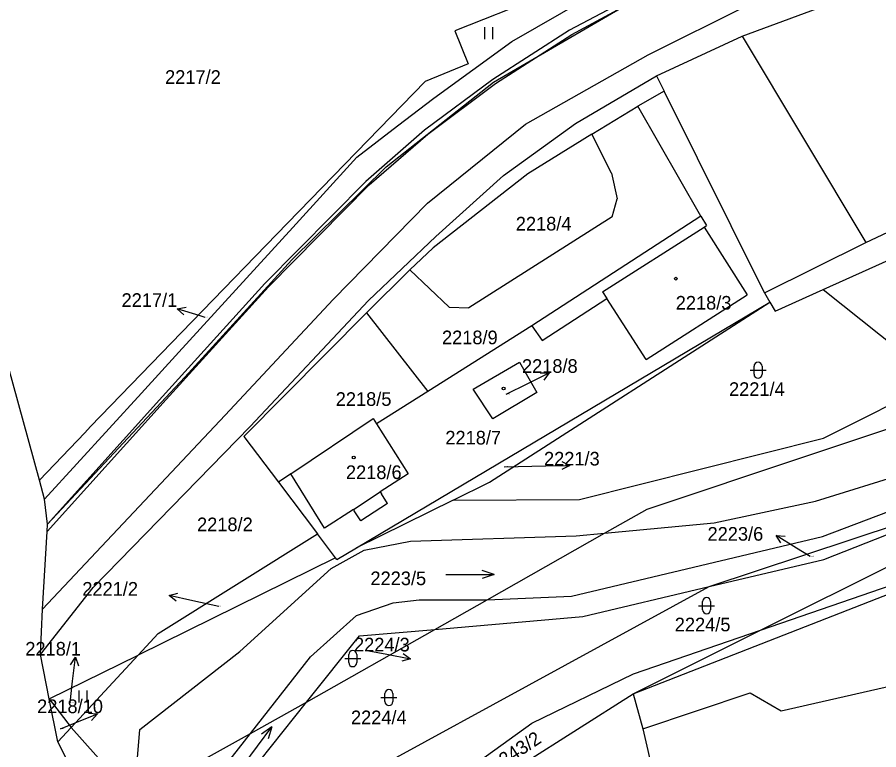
# Model space of a CAD drawing. Extents: x -785744 to -782822, y -1067550 to -1063910.
# Drawn here: x -785532.1 to -785424.6, y -1066082.7 to -1065991.3 of the extents above; entities that cross this region are included whole.
import ezdxf

# ---------------------------------------------------------------- set-up
doc = ezdxf.new("R2010")
doc.units = 0
for name, color, linetype in [('Hranice obce', 7, 'Continuous'), ('Hranice parcel', 7, 'Continuous'), ('Parcelní čísla', 7, 'Continuous'), ('Pop_ČP_popisy', 7, 'Continuous'), ('Vnitřní kresba', 7, 'Continuous'), ('Věcná břemena k části', 7, 'Continuous'), ('Značky budov', 7, 'Continuous'), ('Značky kultur', 7, 'Continuous')]:
    doc.layers.add(name, color=color, linetype=linetype)

msp = doc.modelspace()

# ---------------------------------------------------------------- linework, layer by layer
at = {"layer": 'Hranice obce'}
msp.add_lwpolyline([(-785463.7, -1066190.46), (-785474.61, -1066162.9), (-785474.19, -1066161.18), (-785473.44, -1066158.13), (-785474.61, -1066156.09), (-785475.38, -1066154.75), (-785500.81, -1066110.59), (-785512.84, -1066109.97), (-785514.67, -1066106.33), (-785518.6, -1066098.53), (-785527.03, -1066081.76), (-785528.1, -1066076.38), (-785529.19, -1066070.86), (-785528.96, -1066065.19), (-785528.38, -1066055.51), (-785528.32, -1066054.57), (-785528.68, -1066051.48), (-785529.33, -1066049.1), (-785548.51, -1065979.33)], dxfattribs=at)
at = {"layer": 'Hranice parcel'}
for p, q in [((-785458.69, -1065985.57), (-785477.49, -1065993.04)), ((-785477.49, -1065993.04), (-785475.81, -1065997.17)), ((-785475.81, -1065997.17), (-785481.19, -1065999.34)), ((-785481.19, -1065999.34), (-785498.37, -1066017.04)), ((-785498.37, -1066017.04), (-785510.3, -1066029.34)), ((-785510.3, -1066029.34), (-785522.95, -1066042.39)), ((-785522.95, -1066042.39), (-785523.65, -1066043.21)), ((-785529.33, -1066049.1), (-785523.65, -1066043.21))]:
    msp.add_line(p, q, dxfattribs=at)
for points in [[(-785470.37, -1065994.38), (-785457.89, -1065987.19)], [(-785441.63, -1065993.71), (-785425.3, -1065987.61)], [(-785452.32, -1065998.66), (-785441.63, -1065993.71)], [(-785480.11, -1066001.42), (-785470.37, -1065994.38)], [(-785462.42, -1066004.61), (-785452.32, -1065998.66)], [(-785452.32, -1065998.66), (-785451.36, -1066000.58)], [(-785451.36, -1066000.58), (-785454.65, -1066002.42)], [(-785438.86, -1066025.74), (-785451.36, -1066000.58)], [(-785484.63, -1066004.89), (-785480.11, -1066001.42)], [(-785460.37, -1066005.95), (-785454.65, -1066002.42)], [(-785446.78, -1066016.18), (-785454.65, -1066002.42)], [(-785431.54, -1066025.31), (-785381.44, -1066002.79)], [(-785489.72, -1066008.81), (-785484.63, -1066004.89)], [(-785471.42, -1066011.07), (-785462.42, -1066004.61)], [(-785460.37, -1066005.95), (-785468.36, -1066010.88)], [(-785457.92, -1066010.8), (-785460.37, -1066005.95)], [(-785497.71, -1066017.57), (-785489.72, -1066008.81)], [(-785468.36, -1066010.88), (-785480.18, -1066020.1)], [(-785457.92, -1066010.8), (-785457.22, -1066014)], [(-785479.86, -1066018.68), (-785471.42, -1066011.07)], [(-785457.86, -1066016.26), (-785457.22, -1066014)], [(-785457.86, -1066016.26), (-785475.75, -1066027.6)], [(-785446.78, -1066016.18), (-785446.06, -1066017.32)], [(-785446.39, -1066017.53), (-785446.06, -1066017.32)], [(-785511.95, -1066033.12), (-785497.71, -1066017.57)], [(-785459.04, -1066025.6), (-785446.39, -1066017.53)], [(-785446.39, -1066017.53), (-785441.01, -1066025.96)], [(-785488.28, -1066026.7), (-785479.86, -1066018.68)], [(-785483.09, -1066022.85), (-785480.18, -1066020.1)], [(-785483.09, -1066022.85), (-785488.51, -1066028.24)], [(-785478.2, -1066027.53), (-785483.09, -1066022.85)], [(-785459.04, -1066025.6), (-785458.5, -1066026.44)], [(-785453.63, -1066034.04), (-785441.01, -1066025.96)], [(-785438.86, -1066025.74), (-785438.18, -1066026.89)], [(-785437.53, -1066028), (-785431.54, -1066025.31)], [(-785431.54, -1066025.31), (-785417.21, -1066036.72)], [(-785503.01, -1066042.42), (-785488.28, -1066026.7)], [(-785489.78, -1066057.53), (-785438.18, -1066026.89)], [(-785473.16, -1066049.36), (-785438.18, -1066026.89)], [(-785466.6, -1066031.69), (-785458.5, -1066026.44)], [(-785453.63, -1066034.04), (-785458.5, -1066026.44)], [(-785438.18, -1066026.89), (-785437.53, -1066028)], [(-785478.2, -1066027.53), (-785475.75, -1066027.6)], [(-785503.84, -1066043.65), (-785488.51, -1066028.24)], [(-785488.51, -1066028.24), (-785480.87, -1066038.03)], [(-785467.89, -1066029.83), (-785480.87, -1066038.03)], [(-785467.89, -1066029.83), (-785466.6, -1066031.69)], [(-785516.61, -1066038.24), (-785511.95, -1066033.12)], [(-785475.18, -1066037.74), (-785469.43, -1066034.37)], [(-785469.43, -1066034.37), (-785467.26, -1066038.18)], [(-785431.47, -1066043.85), (-785417.21, -1066036.72)], [(-785472.76, -1066041.45), (-785475.18, -1066037.74)], [(-785528.68, -1066051.48), (-785516.61, -1066038.24)], [(-785480.87, -1066038.03), (-785487.27, -1066042.08)], [(-785467.26, -1066038.18), (-785472.76, -1066041.45)], [(-785453.5, -1066052.7), (-785413.77, -1066039.46)], [(-785497.96, -1066048.32), (-785487.7, -1066041.41)], [(-785487.7, -1066041.41), (-785487.27, -1066042.08)], [(-785487.27, -1066042.08), (-785483.32, -1066048.3)], [(-785522.62, -1066062.51), (-785503.01, -1066042.42)], [(-785503.84, -1066043.65), (-785499.51, -1066049.36)], [(-785461.92, -1066051.53), (-785431.47, -1066043.85)], [(-785445.73, -1066062.38), (-785392.33, -1066044.7)], [(-785497.96, -1066048.32), (-785499.51, -1066049.36)], [(-785493.75, -1066055.11), (-785497.96, -1066048.32)], [(-785483.32, -1066048.3), (-785486.8, -1066050.57)], [(-785499.51, -1066049.36), (-785494.64, -1066055.79)], [(-785477.71, -1066051.59), (-785473.16, -1066049.36)], [(-785486.8, -1066050.57), (-785486.65, -1066050.8)], [(-785477.71, -1066051.59), (-785489.78, -1066057.53)], [(-785485.87, -1066052), (-785486.65, -1066050.8)], [(-785477.71, -1066051.59), (-785461.92, -1066051.53)], [(-785490.15, -1066052.76), (-785493.75, -1066055.11)], [(-785490.15, -1066052.76), (-785490.04, -1066052.92)], [(-785485.87, -1066052), (-785489.22, -1066054.18)], [(-785458.8, -1066055.71), (-785453.5, -1066052.7)], [(-785439.33, -1066067.8), (-785395.25, -1066052.64)], [(-785489.22, -1066054.18), (-785490.04, -1066052.92)], [(-785514.5, -1066068.22), (-785494.64, -1066055.79)], [(-785492.36, -1066058.8), (-785494.64, -1066055.79)], [(-785473.45, -1066064.02), (-785458.8, -1066055.71)], [(-785431.45, -1066058.99), (-785423.62, -1066055.94)], [(-785492.22, -1066058.98), (-785489.78, -1066057.53)], [(-785492.36, -1066058.8), (-785517, -1066070.92)], [(-785492.22, -1066058.98), (-785492.36, -1066058.8)], [(-785445.73, -1066062.38), (-785431.45, -1066058.99)], [(-785439.33, -1066067.8), (-785422.26, -1066059.29)], [(-785436.75, -1066077.9), (-785361.64, -1066060.8)], [(-785529.19, -1066070.86), (-785522.62, -1066062.51)], [(-785508.19, -1066096.46), (-785445.73, -1066062.38)], [(-785461.5, -1066066.13), (-785445.73, -1066062.38)], [(-785455.25, -1066075.75), (-785420.43, -1066062.14)], [(-785479.98, -1066067.73), (-785473.45, -1066064.02)], [(-785479.98, -1066067.73), (-785461.5, -1066066.13)], [(-785496.01, -1066076.82), (-785479.98, -1066067.73)], [(-785489.4, -1066068.54), (-785479.98, -1066067.73)], [(-785455.25, -1066075.75), (-785439.33, -1066067.8)], [(-785455.21, -1066073.27), (-785439.33, -1066067.8)], [(-785517, -1066070.92), (-785514.5, -1066068.22)], [(-785496.01, -1066076.82), (-785489.4, -1066068.54)], [(-785528.1, -1066076.38), (-785517, -1066070.92)], [(-785525.37, -1066079.96), (-785517, -1066070.92)], [(-785467.89, -1066079.4), (-785455.21, -1066073.27)], [(-785528.1, -1066076.38), (-785525.37, -1066079.96)], [(-785476.06, -1066089), (-785455.25, -1066075.75)], [(-785455.25, -1066075.75), (-785454.03, -1066080.13)], [(-785454.03, -1066080.13), (-785440.61, -1066075.63)], [(-785440.61, -1066075.63), (-785436.75, -1066077.9)], [(-785506.21, -1066089.6), (-785496.01, -1066076.82)], [(-785502.98, -1066080.7), (-785496.01, -1066076.82)], [(-785479.21, -1066087.57), (-785467.89, -1066079.4)], [(-785527.03, -1066081.76), (-785525.37, -1066079.96)], [(-785525.37, -1066079.96), (-785517.51, -1066088.78)], [(-785517.51, -1066088.78), (-785502.98, -1066080.7)], [(-785454.03, -1066080.13), (-785446.87, -1066111.18)]]:
    msp.add_lwpolyline(points, dxfattribs=at)
at = {"layer": 'Pop_ČP_popisy'}
for p, q in [((-785509.26, -1066028.61), (-785512.12, -1066027.71)), ((-785468.39, -1066037.05), (-785465.7, -1066035.72)), ((-785466.13, -1066047.33), (-785463.13, -1066047.27)), ((-785434.84, -1066057.57), (-785437.39, -1066055.99)), ((-785510.2, -1066064.14), (-785513.13, -1066063.5)), ((-785485.98, -1066070.82), (-785483.04, -1066071.39)), ((-785525.19, -1066074.18), (-785524.84, -1066071.2)), ((-785524.88, -1066079.38), (-785522.1, -1066078.25))]:
    msp.add_line(p, q, dxfattribs=at)
for points in [[(-785511.32, -1066028.49), (-785512.12, -1066027.71), (-785511.02, -1066027.53)], [(-785508.64, -1066028.8), (-785509.26, -1066028.61)], [(-785466.82, -1066035.71), (-785465.7, -1066035.72), (-785466.38, -1066036.61)], [(-785471.07, -1066038.38), (-785468.39, -1066037.05)], [(-785471.32, -1066047.44), (-785466.13, -1066047.33)], [(-785464.14, -1066046.79), (-785463.13, -1066047.27), (-785464.12, -1066047.79)], [(-785436.8, -1066056.94), (-785437.39, -1066055.99), (-785436.28, -1066056.09)], [(-785433.13, -1066058.63), (-785434.84, -1066057.57)], [(-785512.26, -1066064.2), (-785513.13, -1066063.5), (-785512.05, -1066063.22)], [(-785506.96, -1066064.85), (-785510.2, -1066064.14)], [(-785488.22, -1066070.38), (-785485.98, -1066070.82)], [(-785483.92, -1066070.71), (-785483.04, -1066071.39), (-785484.11, -1066071.69)], [(-785525.46, -1066072.14), (-785524.84, -1066071.2), (-785524.46, -1066072.25)], [(-785525.5, -1066076.88), (-785525.19, -1066074.18)], [(-785523.22, -1066078.16), (-785522.1, -1066078.25), (-785522.84, -1066079.09)], [(-785526.72, -1066080.13), (-785524.88, -1066079.38)]]:
    msp.add_lwpolyline(points, dxfattribs=at)
at = {"layer": 'Vnitřní kresba'}
for points in [[(-785472.66, -1065999.43), (-785456.64, -1065990.12)], [(-785453.34, -1065996.02), (-785441.02, -1065989.88)], [(-785441.63, -1065993.71), (-785426.19, -1066019.46)], [(-785468.67, -1066004.7), (-785453.34, -1065996.02)], [(-785426.19, -1066019.46), (-785378.73, -1065997.17)], [(-785486.04, -1066010.01), (-785472.66, -1065999.43)], [(-785480.9, -1066014.52), (-785468.67, -1066004.7)], [(-785497.81, -1066021.6), (-785486.04, -1066010.01)], [(-785492.68, -1066026.57), (-785480.9, -1066014.52)], [(-785446.78, -1066016.18), (-785467.89, -1066029.83)], [(-785438.86, -1066025.74), (-785426.19, -1066019.46)], [(-785511.17, -1066036.23), (-785497.81, -1066021.6)], [(-785506.17, -1066040.99), (-785492.68, -1066026.57)], [(-785528.32, -1066054.57), (-785511.17, -1066036.23)], [(-785528.96, -1066065.19), (-785506.17, -1066040.99)], [(-785432.47, -1066051.72), (-785420.94, -1066048.16)], [(-785431.61, -1066056.15), (-785410.83, -1066048.25)], [(-785490.15, -1066052.76), (-785486.8, -1066050.57)], [(-785445.12, -1066054.43), (-785432.47, -1066051.72)], [(-785458.8, -1066055.71), (-785445.12, -1066054.43)], [(-785483.01, -1066056.73), (-785462.35, -1066056.04)], [(-785462.35, -1066056.04), (-785458.8, -1066055.71)], [(-785488.8, -1066057.85), (-785483.01, -1066056.73)], [(-785462.93, -1066063.57), (-785431.61, -1066056.15)], [(-785492.91, -1066060.14), (-785488.8, -1066057.85)], [(-785504.32, -1066070.46), (-785492.91, -1066060.14)], [(-785473.45, -1066064.02), (-785462.93, -1066063.57)], [(-785489.75, -1066065.99), (-785485.19, -1066064.42)], [(-785485.19, -1066064.42), (-785481.94, -1066064.02)], [(-785481.94, -1066064.02), (-785473.45, -1066064.02)], [(-785495.49, -1066071.13), (-785489.75, -1066065.99)], [(-785516.78, -1066080.22), (-785504.32, -1066070.46)], [(-785502.98, -1066080.7), (-785495.49, -1066071.13)], [(-785517.51, -1066088.78), (-785516.78, -1066080.22)], [(-785508.22, -1066087.39), (-785502.98, -1066080.7)]]:
    msp.add_lwpolyline(points, dxfattribs=at)
at = {"layer": 'Věcná břemena k části'}
for points in [[(-785452.97, -1065987.56), (-785463.17, -1065992.96)], [(-785462.87, -1065993.48), (-785456.64, -1065990.12)], [(-785463.17, -1065992.96), (-785472.75, -1065999.11)], [(-785472.41, -1065999.61), (-785462.87, -1065993.48)], [(-785472.75, -1065999.11), (-785481.28, -1066005.41)], [(-785480.86, -1066005.92), (-785472.41, -1065999.61)], [(-785481.28, -1066005.41), (-785488.61, -1066011.82)], [(-785488.19, -1066012.26), (-785480.86, -1066005.92)], [(-785488.61, -1066011.82), (-785501.18, -1066024.56)], [(-785500.74, -1066024.98), (-785488.19, -1066012.26)], [(-785501.18, -1066024.56), (-785513.97, -1066038.65)], [(-785513.53, -1066039.05), (-785500.74, -1066024.98)], [(-785513.97, -1066038.65), (-785528.32, -1066054.57)], [(-785528.38, -1066055.51), (-785513.53, -1066039.05)]]:
    msp.add_lwpolyline(points, dxfattribs=at)
at = {"layer": 'Značky budov'}
for centre in [(-785449.9, -1066023.96), (-785471.4, -1066037.66), (-785490.11, -1066046.28)]:
    msp.add_circle(centre, 0.175, dxfattribs=at)
at = {"layer": 'Značky kultur'}
for p, q in [((-785473.73, -1065994.06), (-785473.73, -1065992.56)), ((-785472.73, -1065994.06), (-785472.73, -1065992.56)), ((-785440.65, -1066035.39), (-785438.65, -1066035.39)), ((-785440.15, -1066035.89), (-785440.15, -1066034.89)), ((-785439.15, -1066034.89), (-785439.15, -1066035.89)), ((-785446.57, -1066065.26), (-785446.57, -1066064.26)), ((-785445.57, -1066064.26), (-785445.57, -1066065.26)), ((-785447.07, -1066064.76), (-785445.07, -1066064.76)), ((-785490.72, -1066071.87), (-785490.72, -1066070.87)), ((-785489.72, -1066070.87), (-785489.72, -1066071.87)), ((-785491.22, -1066071.37), (-785489.22, -1066071.37)), ((-785524.38, -1066076.85), (-785524.38, -1066075.35)), ((-785523.38, -1066076.85), (-785523.38, -1066075.35)), ((-785486.71, -1066076.23), (-785484.71, -1066076.23)), ((-785486.21, -1066076.73), (-785486.21, -1066075.73)), ((-785485.21, -1066075.73), (-785485.21, -1066076.73))]:
    msp.add_line(p, q, dxfattribs=at)
for points in [[(-785478.59, -1066060.86), (-785472.59, -1066060.86), (-785474.09, -1066060.36)], [(-785472.59, -1066060.86), (-785474.09, -1066061.36)], [(-785503.89, -1066084.69), (-785500.31, -1066079.89), (-785501.6, -1066080.79)], [(-785500.31, -1066079.89), (-785500.8, -1066081.39)]]:
    msp.add_lwpolyline(points, dxfattribs=at)
for centre, start, end in [((-785439.65, -1066034.89), 0, 180), ((-785439.65, -1066035.89), 180, 0), ((-785446.07, -1066064.26), 0, 180), ((-785446.07, -1066065.26), 180, 0), ((-785490.22, -1066070.87), 0, 180), ((-785490.22, -1066071.87), 180, 0), ((-785485.71, -1066075.73), 0, 180), ((-785485.71, -1066076.73), 180, 0)]:
    msp.add_arc(centre, 0.5, start, end, dxfattribs=at)

# ---------------------------------------------------------------- texts
at = {"layer": 'Parcelní čísla'}
for s, height, p in [('2217/2', 1.7, (-785513.65, -1065999.65)), ('2218/4', 1.7, (-785469.88, -1066017.95)), ('2218/3', 1.7, (-785449.92, -1066027.82)), ('2217/1', 0.1, (-785508.64, -1066028.8)), ('2218/9', 1.7, (-785479.09, -1066032.14)), ('2221/4', 1.7, (-785443.27, -1066038.59)), ('2218/5', 1.7, (-785492.35, -1066039.83)), ('2218/8', 0.1, (-785471.07, -1066038.38)), ('2218/7', 1.7, (-785478.67, -1066044.65)), ('2218/6', 1.7, (-785491.08, -1066048.96)), ('2221/3', 0.1, (-785471.32, -1066047.44)), ('2218/2', 1.7, (-785509.66, -1066055.47)), ('2223/6', 0.1, (-785433.13, -1066058.63)), ('2223/5', 1.7, (-785488.02, -1066062.2)), ('2221/2', 0.1, (-785506.96, -1066064.85)), ('2224/5', 1.7, (-785450.04, -1066067.96)), ('2224/3', 0.1, (-785488.22, -1066070.38)), ('2218/1', 0.1, (-785525.5, -1066076.88)), ('2224/4', 1.7, (-785490.45, -1066079.55)), ('2218/10', 0.1, (-785526.72, -1066080.13))]:
    msp.add_text(s, height=height, dxfattribs=at).set_placement(p)
msp.add_text('2243/2', height=1.7, rotation=33.3868, dxfattribs=at).set_placement((-785472.34, -1066085.58))
at = {"layer": 'Pop_ČP_popisy'}
for s, p in [('2217/1', (-785519.08, -1066027.48)), ('2218/8', (-785469.11, -1066035.71)), ('2221/3', (-785466.36, -1066047.27)), ('2223/6', (-785445.95, -1066056.65)), ('2221/2', (-785523.98, -1066063.51)), ('2224/3', (-785490.07, -1066070.47)), ('2218/1', (-785531.09, -1066070.99)), ('2218/10', (-785529.62, -1066078.17))]:
    msp.add_text(s, height=1.7, dxfattribs=at).set_placement(p)

doc.saveas('drawing.dxf')
